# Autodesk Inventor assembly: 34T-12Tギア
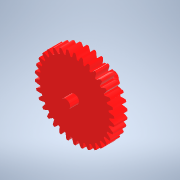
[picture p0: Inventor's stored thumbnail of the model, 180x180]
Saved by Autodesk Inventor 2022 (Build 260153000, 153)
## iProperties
Created: 2024-10
Part Number: 34T-12Tギア
Document SubType Name: Assembly
Designer: shimizu
Author: shimizu
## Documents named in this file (3)
- C:\Users\shimizu\Documents\卒論2024\3DCAD\ギアボックス\部品図\34T-12Tギア.iam
- C:\Users\shimizu\Documents\卒論2024\3DCAD\ギアボックス\部品図\34Tギア.ipt
- C:\Users\shimizu\Documents\卒論2024\3DCAD\ギアボックス\部品図\12Tギア.ipt
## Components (2 placed, 1 different names)
1. 平歯車1:1 — リジッド:1
2. 平歯車1:2 — リジッド:1
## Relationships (1: WeldJoint 1)
- リジッド:1 [WeldJoint]: 平歯車1:1 ↔ 平歯車1:2
